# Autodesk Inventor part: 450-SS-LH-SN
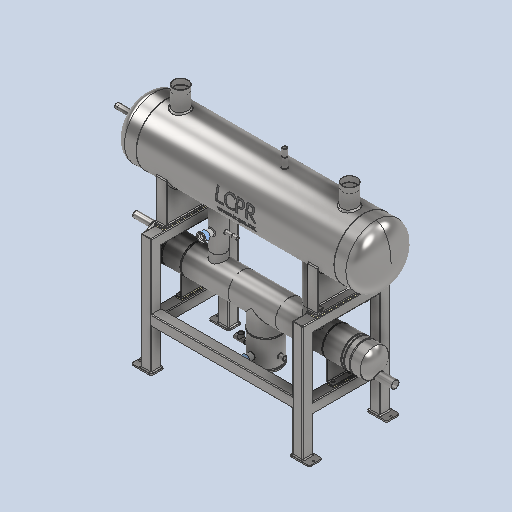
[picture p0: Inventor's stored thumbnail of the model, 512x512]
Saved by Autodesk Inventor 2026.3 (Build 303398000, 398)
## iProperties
Created: 2026-05
Part Number: 450-SS-LH-SN
Material: Generic
Document SubType Name: Modeling
Designer: rva
Density: 1 g/cm^3
Appearance: Default
Author: rva
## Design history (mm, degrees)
derived "450-SS-LH-SN.iam"
body "Solid1"
node "Nylon Heat Tranfer Spacer 175x50.ipt:1"
node "Nylon Heat Tranfer Spacer 175x50.ipt:2"
node "Nylon Heat Tranfer Spacer 460x75.ipt:1"
node "Nylon Heat Tranfer Spacer 460x75.ipt:2"
node "Sub-SS-200-100-1370-48-10-50-40-WELD.iam:1::LCPR-200 SS Blan"
node "Sub-SS-200-100-1370-48-10-50-40-WELD.iam:1::SS-200 mm Subcoo"
node "Sub-SS-200-100-1370-48-10-50-40-WELD.iam:1::SS-200 mm Subcoo"
node "Sub-SS-200-100-1370-48-10-50-40-WELD.iam:1::DIN 2462 Tube 10"
node "Sub-SS-200-100-1370-48-10-50-40-WELD.iam:1::DIN 2462 Tube 10"
node "Sub-SS-200-100-1370-48-10-50-40-WELD.iam:1::DIN 2462 Tube 10"
node "Sub-SS-200-100-1370-48-10-50-40-WELD.iam:1::DIN 2462 Tube 10"
node "Sub-SS-200-100-1370-48-10-50-40-WELD.iam:1::H1100-R.ipt:1"
node "Sub-SS-200-100-1370-48-10-50-40-WELD.iam:1::H1100-R.ipt:2"
node "Sub-SS-200-100-1370-48-10-50-40-WELD.iam:1::1-2 Inch NPT Soc"
node "Sub-SS-200-100-1370-48-10-50-40-WELD.iam:1::3-4 Inch NPT Soc"
node "Sub-SS-200-100-1370-48-10-50-40-WELD.iam:1::1-2 Inch NPT Soc"
node "Sub-SS-200-100-1370-48-10-50-40-WELD.iam:1::Welds"
node "LCPR-SS-450-1500-100-SP-WELD.iam:1::H1100-R.ipt:1"
node "LCPR-SS-450-1500-100-SP-WELD.iam:1::450 mm SS Dome Cap.ipt:1"
node "LCPR-SS-450-1500-100-SP-WELD.iam:1::450 mm SS Dome Cap.ipt:2"
node "LCPR-SS-450-1500-100-SP-WELD.iam:1::Welds"
node "AS 1112 (2) - Metric M16  Type 10:1"
node "AS 1237 (4.1) 16 mm:1"
node "AS 1237 (4.1) 16 mm:2"
node "AS 1112 (2) - Metric M16  Type 10:2"
node "AS 1237 (4.1) 16 mm:3"
node "AS 1237 (4.1) 16 mm:4"
node "AS 1252 - Metric M16 x 120:2"
node "AS 1112 (2) - Metric M16  Type 10:3"
node "AS 1237 (4.1) 16 mm:5"
node "AS 1237 (4.1) 16 mm:6"
node "AS 1252 - Metric M16 x 120:3"
node "AS 1112 (2) - Metric M16  Type 10:4"
node "AS 1237 (4.1) 16 mm:7"
node "AS 1237 (4.1) 16 mm:8"
node "AS 1252 - Metric M16 x 120:4"
node "AS 1112 (2) - Metric M10  Type 10:1"
node "AS 1237 (D1) 10 mm:1"
node "AS 1237 (D1) 10 mm:2"
node "AS 1111 - Metric M10 x 120:1"
node "AS 1112 (2) - Metric M10  Type 10:2"
node "AS 1237 (D1) 10 mm:3"
node "AS 1237 (D1) 10 mm:4"
node "AS 1111 - Metric M10 x 120:2"
node "AS 1112 (2) - Metric M10  Type 10:3"
node "AS 1237 (D1) 10 mm:5"
node "AS 1237 (D1) 10 mm:6"
node "AS 1111 - Metric M10 x 120:3"
node "AS 1112 (2) - Metric M10  Type 10:4"
node "AS 1237 (D1) 10 mm:7"
node "AS 1237 (D1) 10 mm:8"
node "AS 1111 - Metric M10 x 120:4"
node "Welds"
node "AS 1252 - Metric M16 x 120:5"
node "450-SS-LH-SN.iam_Bodies"
